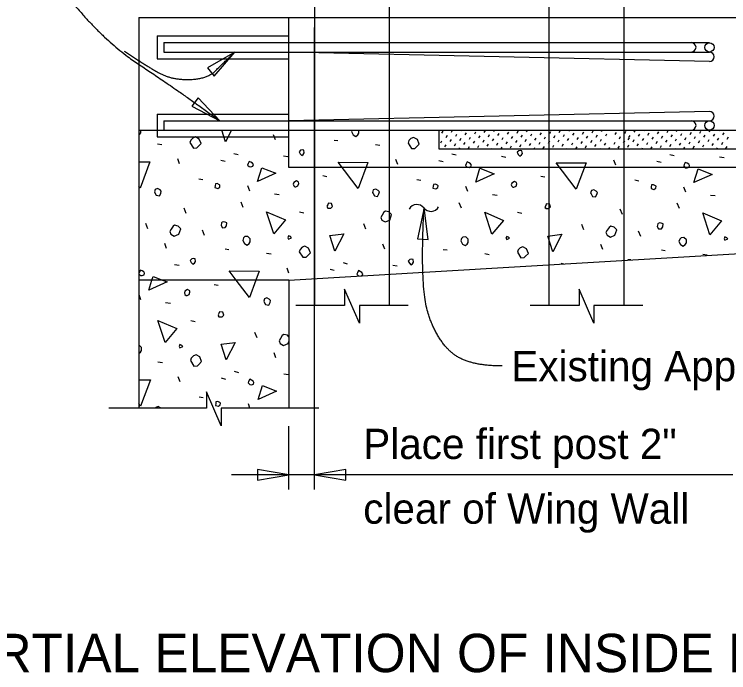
# Model space of a CAD drawing. Extents: x 1.5 to 68.7, y 0 to 31.
# Drawn here: x 5.708 to 10.468, y 8.928 to 13.319 of the extents above; entities that cross this region are included whole.
import ezdxf

# ---------------------------------------------------------------- set-up
doc = ezdxf.new("R2010")
doc.units = 0
for name, color, linetype in [('AdhocPoint_dp', 7, 'Continuous'), ('Border', 7, 'Continuous'), ('Patterning', 7, 'Continuous'), ('PlotBorder_dp', 7, 'Continuous'), ('TextMisc', 7, 'Continuous')]:
    doc.layers.add(name, color=color, linetype=linetype)

msp = doc.modelspace()

# ---------------------------------------------------------------- linework, layer by layer
at = {"layer": 'AdhocPoint_dp'}
for p, q in [((7.7082, 10.1491), (7.7082, 13.2304)), ((7.5373, 10.1491), (7.5373, 10.5717)), ((10.4962, 10.2486), (7.1558, 10.2486))]:
    msp.add_line(p, q, dxfattribs=at)
for points in [[(7.1773, 13.0672), (6.9947, 12.961), (7.0399, 12.9068)], [(7.0775, 12.6089), (6.9327, 12.7627), (6.8901, 12.7064)], [(8.438, 12.0275), (8.3942, 11.8209), (8.4647, 11.818)], [(7.5373, 10.2486), (7.3291, 10.2839), (7.3291, 10.2133)], [(7.7083, 10.2486), (7.9165, 10.2133), (7.9165, 10.2839)]]:
    msp.add_lwpolyline(points, close=True, dxfattribs=at)
for points in [[(8.3333, 11.3762), (8.008, 11.3762), (8.008, 11.2599), (7.9086, 11.4849), (7.9086, 11.3762), (7.5833, 11.3762)], [(9.8958, 11.3762), (9.5705, 11.3762), (9.5705, 11.2599), (9.4711, 11.4849), (9.4711, 11.3762), (9.1458, 11.3762)], [(7.7373, 10.6916), (7.087, 10.6916), (7.087, 10.5754), (6.9877, 10.8004), (6.9877, 10.6916), (6.3373, 10.6916)]]:
    msp.add_lwpolyline(points, dxfattribs=at)
for centre, start, end in [((8.3903, 11.9906), 38.2108, 149.938), ((8.484, 12.0643), 218.2108, 329.938)]:
    msp.add_arc(centre, 0.0596, start, end, dxfattribs=at)
for points in [[(6.8093, 15.9088), (6.0612, 15.8929), (5.9024, 15.7817), (5.8017, 15.236), (5.8706, 13.668), (6.3154, 13.1303), (6.7761, 12.8283), (7.0775, 12.6089)], [(6.4408, 13.0737), (6.5854, 12.9767), (6.7549, 12.8813), (6.9932, 12.8866), (7.1044, 12.9978), (7.1773, 13.0672)], [(8.9586, 10.9737), (8.7125, 10.9737), (8.5074, 11.1744), (8.4117, 11.5165), (8.4379, 12.0275)]]:
    msp.add_open_spline(points, degree=2, dxfattribs=at)
at = {"layer": 'Border'}
for p, q in [((6.704, 13.1297), (10.3395, 13.1297)), ((6.704, 13.1297), (6.704, 13.0672)), ((6.704, 13.0672), (10.3395, 13.0672)), ((10.3395, 13.0048), (7.5373, 13.0672)), ((10.3395, 12.6713), (7.5373, 12.6089)), ((6.704, 12.6089), (10.3395, 12.6089)), ((6.704, 12.6089), (6.704, 12.5464)), ((6.704, 12.5464), (10.3395, 12.5464))]:
    msp.add_line(p, q, dxfattribs=at)
for centre in [(10.3395, 13.0984), (10.3395, 12.5776)]:
    msp.add_circle(centre, 0.0312, dxfattribs=at)
for centre in [(10.2192, 13.0985), (10.3395, 13.036), (10.3395, 13.036), (10.3395, 12.6401), (10.2192, 12.5777)]:
    msp.add_arc(centre, 0.0312, 270, 90, dxfattribs=at)
at = {"layer": 'Patterning'}
for p, q in [((8.5578, 12.5255), (8.5659, 12.5395)), ((8.6213, 12.5336), (8.6287, 12.5464)), ((8.6848, 12.5417), (8.6875, 12.5464)), ((8.7125, 12.514), (8.7206, 12.528)), ((8.776, 12.5221), (8.7841, 12.5361)), ((8.8395, 12.5302), (8.8476, 12.5442)), ((8.903, 12.5383), (8.9076, 12.5464)), ((8.9307, 12.5106), (8.9388, 12.5246)), ((8.9942, 12.5187), (9.0023, 12.5327)), ((9.0577, 12.5268), (9.0658, 12.5408)), ((9.1211, 12.5349), (9.1278, 12.5464)), ((9.1488, 12.5073), (9.1569, 12.5212)), ((9.1846, 12.543), (9.1866, 12.5464)), ((9.2123, 12.5154), (9.2204, 12.5293)), ((9.2758, 12.5235), (9.2839, 12.5374)), ((9.3393, 12.5316), (9.3474, 12.5456)), ((9.4028, 12.5397), (9.4067, 12.5464)), ((9.4305, 12.512), (9.4386, 12.526)), ((9.494, 12.5201), (9.5021, 12.5341)), ((9.5575, 12.5282), (9.5656, 12.5422)), ((9.621, 12.5363), (9.6268, 12.5464)), ((9.6487, 12.5086), (9.6568, 12.5226)), ((9.6845, 12.5444), (9.6856, 12.5464)), ((9.7122, 12.5167), (9.7203, 12.5307)), ((9.7757, 12.5248), (9.7838, 12.5388)), ((9.8392, 12.5329), (9.847, 12.5464)), ((9.9026, 12.541), (9.9058, 12.5464)), ((9.9303, 12.5133), (9.9384, 12.5273)), ((9.9938, 12.5214), (10.0019, 12.5354)), ((10.0573, 12.5295), (10.0654, 12.5435)), ((10.1208, 12.5376), (10.1259, 12.5464)), ((10.1485, 12.5099), (10.1566, 12.5239)), ((10.1843, 12.5457), (10.1847, 12.5464)), ((10.212, 12.518), (10.2201, 12.532)), ((10.2755, 12.5261), (10.2836, 12.5401)), ((10.339, 12.5342), (10.346, 12.5464)), ((10.3667, 12.5065), (10.3748, 12.5205)), ((10.4025, 12.5423), (10.4048, 12.5464)), ((10.4302, 12.5146), (10.4383, 12.5286)), ((7.4477, 12.4815), (7.4354, 12.515)), ((7.8384, 12.4797), (7.8632, 12.4762)), ((8.5497, 12.462), (8.5578, 12.476)), ((8.5855, 12.4978), (8.5936, 12.5118)), ((8.6132, 12.4701), (8.6213, 12.4841)), ((8.649, 12.5059), (8.6571, 12.5199)), ((8.6767, 12.4782), (8.6848, 12.4922)), ((8.7402, 12.4863), (8.7483, 12.5003)), ((8.7679, 12.4586), (8.776, 12.4726)), ((8.8037, 12.4944), (8.8118, 12.5084)), ((8.8314, 12.4667), (8.8395, 12.4807)), ((8.8672, 12.5025), (8.8753, 12.5165)), ((8.8949, 12.4748), (8.903, 12.4888)), ((8.9584, 12.4829), (8.9665, 12.4969)), ((9.0219, 12.491), (9.03, 12.505)), ((9.0496, 12.4634), (9.0577, 12.4773)), ((9.0854, 12.4991), (9.0935, 12.5131)), ((9.113, 12.4715), (9.1211, 12.4854)), ((9.1765, 12.4796), (9.1846, 12.4936)), ((9.24, 12.4877), (9.2481, 12.5017)), ((9.2677, 12.46), (9.2758, 12.474)), ((9.3035, 12.4958), (9.3116, 12.5098)), ((9.3312, 12.4681), (9.3393, 12.4821)), ((9.367, 12.5039), (9.3751, 12.5179)), ((9.3947, 12.4762), (9.4028, 12.4902)), ((9.4582, 12.4843), (9.4663, 12.4983)), ((9.5217, 12.4924), (9.5298, 12.5064)), ((9.5494, 12.4647), (9.5575, 12.4787)), ((9.5852, 12.5005), (9.5933, 12.5145)), ((9.6129, 12.4728), (9.621, 12.4868)), ((9.7399, 12.489), (9.748, 12.503)), ((9.7676, 12.4613), (9.7757, 12.4753)), ((9.7989, 12.4809), (9.807, 12.4949)), ((9.8034, 12.4971), (9.8115, 12.5111)), ((9.8311, 12.4694), (9.8392, 12.4834)), ((9.8669, 12.5052), (9.875, 12.5192)), ((9.8945, 12.4775), (9.9026, 12.4915)), ((9.958, 12.4856), (9.9661, 12.4996)), ((10.0215, 12.4937), (10.0296, 12.5077)), ((10.0492, 12.466), (10.0573, 12.48)), ((10.085, 12.5018), (10.0931, 12.5158)), ((10.1127, 12.4741), (10.1208, 12.4881)), ((10.1762, 12.4822), (10.1843, 12.4962)), ((10.2397, 12.4903), (10.2478, 12.5043)), ((10.2674, 12.4626), (10.2755, 12.4766)), ((10.3032, 12.4984), (10.3113, 12.5124)), ((10.3309, 12.4707), (10.339, 12.4847)), ((10.3944, 12.4788), (10.4025, 12.4928)), ((10.4579, 12.4869), (10.466, 12.5009)), ((6.6611, 12.4549), (6.6911, 12.4496)), ((8.1142, 12.4514), (8.1442, 12.4461)), ((8.5774, 12.4343), (8.5855, 12.4483)), ((8.6409, 12.4424), (8.649, 12.4564)), ((8.6725, 12.4214), (8.6767, 12.4287)), ((8.7044, 12.4505), (8.7125, 12.4645)), ((8.7321, 12.4228), (8.7402, 12.4368)), ((8.7956, 12.4309), (8.8037, 12.4449)), ((8.8591, 12.439), (8.8672, 12.453)), ((8.8926, 12.4214), (8.8949, 12.4253)), ((8.9226, 12.4471), (8.9307, 12.4611)), ((8.9514, 12.4214), (8.9584, 12.4334)), ((8.9861, 12.4552), (8.9942, 12.4692)), ((9.0138, 12.4276), (9.0219, 12.4415)), ((9.0772, 12.4357), (9.0854, 12.4497)), ((9.1407, 12.4438), (9.1488, 12.4578)), ((9.1715, 12.4214), (9.1765, 12.4301)), ((9.2042, 12.4519), (9.2123, 12.4659)), ((9.2319, 12.4242), (9.24, 12.4382)), ((9.2954, 12.4323), (9.3035, 12.4463)), ((9.3589, 12.4404), (9.367, 12.4544)), ((9.3917, 12.4214), (9.3947, 12.4267)), ((9.4224, 12.4485), (9.4305, 12.4625)), ((9.4505, 12.4214), (9.4582, 12.4348)), ((9.4859, 12.4566), (9.494, 12.4706)), ((9.5136, 12.4289), (9.5217, 12.4429)), ((9.5771, 12.437), (9.5852, 12.451)), ((9.6406, 12.4451), (9.6487, 12.4591)), ((9.6706, 12.4214), (9.6764, 12.4314)), ((9.7041, 12.4532), (9.7122, 12.4672)), ((9.7318, 12.4255), (9.7399, 12.4395)), ((9.7953, 12.4336), (9.8034, 12.4476)), ((9.8587, 12.4417), (9.8669, 12.4557)), ((9.8907, 12.4214), (9.8945, 12.428)), ((9.9222, 12.4498), (9.9303, 12.4638)), ((9.9499, 12.4221), (9.958, 12.4361)), ((9.9857, 12.4579), (9.9938, 12.4719)), ((10.0134, 12.4302), (10.0215, 12.4442)), ((10.0769, 12.4383), (10.085, 12.4523)), ((10.1404, 12.4464), (10.1485, 12.4604)), ((10.1697, 12.4214), (10.1762, 12.4327)), ((10.2039, 12.4545), (10.212, 12.4685)), ((10.2316, 12.4268), (10.2397, 12.4408)), ((10.2951, 12.4349), (10.3032, 12.4489)), ((10.3586, 12.443), (10.3667, 12.457)), ((10.3898, 12.4214), (10.3944, 12.4293)), ((10.4221, 12.4511), (10.4302, 12.4651)), ((10.4498, 12.4234), (10.4579, 12.4374)), ((7.1702, 12.3913), (7.1985, 12.3842)), ((8.6233, 12.3878), (8.6516, 12.3807)), ((9.1127, 12.4214), (9.113, 12.422)), ((9.6118, 12.4214), (9.6129, 12.4233)), ((10.0764, 12.3842), (10.1047, 12.3772)), ((10.1109, 12.4214), (10.1127, 12.4246)), ((6.8096, 12.3206), (6.7972, 12.3542)), ((7.0836, 12.3471), (7.1119, 12.34)), ((7.5008, 12.3754), (7.5308, 12.3701)), ((8.2627, 12.3171), (8.2503, 12.3506)), ((8.5367, 12.3436), (8.565, 12.3365)), ((8.9539, 12.3719), (8.9839, 12.3665)), ((9.7158, 12.3135), (9.7034, 12.3471)), ((9.9898, 12.34), (10.0181, 12.333)), ((10.407, 12.3683), (10.437, 12.363)), ((7.7642, 12.2428), (7.7907, 12.2375)), ((9.2173, 12.2393), (9.2438, 12.234)), ((6.9369, 12.2216), (6.9634, 12.2163)), ((8.39, 12.2181), (8.4165, 12.2128)), ((9.8431, 12.2145), (9.8696, 12.2092)), ((7.2763, 12.1403), (7.2639, 12.1739)), ((8.7294, 12.1367), (8.717, 12.1703)), ((10.1825, 12.1332), (10.1701, 12.1668)), ((7.4407, 12.1208), (7.4725, 12.1173)), ((8.8938, 12.1173), (8.9256, 12.1138)), ((10.3469, 12.1138), (10.3787, 12.1102)), ((7.2338, 12.0307), (7.2197, 12.066)), ((8.6869, 12.0271), (8.6728, 12.0625)), ((10.1401, 12.0236), (10.1259, 12.059)), ((6.8538, 11.99), (6.8396, 12.0254)), ((7.6086, 12.0024), (7.6369, 11.9953)), ((9.0617, 11.9989), (9.09, 11.9918)), ((9.76, 11.9829), (9.7458, 12.0183)), ((6.5974, 11.8893), (6.5833, 11.9246)), ((8.0506, 11.8857), (8.0364, 11.9211)), ((9.5037, 11.8822), (9.4895, 11.9175)), ((6.9758, 11.8433), (6.9616, 11.8786)), ((9.882, 11.8362), (9.8678, 11.8716)), ((6.723, 11.7567), (6.7106, 11.7903)), ((8.1761, 11.7531), (8.1637, 11.7867)), ((9.6292, 11.7496), (9.6168, 11.7832)), ((7.1136, 11.7549), (7.1384, 11.7514)), ((7.3894, 11.7266), (7.4195, 11.7213)), ((8.5667, 11.7514), (8.5915, 11.7478)), ((8.8425, 11.7231), (8.8726, 11.7178)), ((10.0198, 11.7478), (10.0446, 11.7443)), ((10.2956, 11.7195), (10.3257, 11.7142)), ((6.776, 11.6506), (6.806, 11.6453)), ((7.5379, 11.5923), (7.5255, 11.6259)), ((7.8119, 11.6188), (7.8402, 11.6117)), ((7.8985, 11.663), (7.9268, 11.6559)), ((8.2291, 11.6471), (8.2591, 11.6418)), ((9.3516, 11.6594), (9.3698, 11.6549)), ((7.0394, 11.518), (7.0659, 11.5127)), ((6.5515, 11.4155), (6.5391, 11.4491)), ((6.7159, 11.396), (6.7477, 11.3925)), ((6.8838, 11.2776), (6.9121, 11.2705)), ((7.3258, 11.1609), (7.3116, 11.1963)), ((7.4513, 11.0283), (7.4389, 11.0619)), ((6.6646, 11.0018), (6.6947, 10.9965)), ((7.1737, 10.9382), (7.202, 10.9311)), ((7.5043, 10.9223), (7.5344, 10.917)), ((6.8131, 10.8675), (6.8007, 10.9011)), ((7.0871, 10.894), (7.1154, 10.8869)), ((6.9404, 10.7685), (6.9669, 10.7632)), ((7.2782, 10.6916), (7.2674, 10.7208))]:
    msp.add_line(p, q, dxfattribs=at)
for points in [[(8.2082, 11.3761), (8.2082, 15.1963), (7.7082, 15.1963), (7.7082, 11.3761)], [(9.7707, 11.3761), (9.7707, 15.1963), (9.2707, 15.1963), (9.2707, 11.3761)], [(6.5373, 12.5133), (6.5444, 12.5186), (6.5515, 12.5292), (6.5515, 12.5464)], [(7.1154, 12.4673), (7.0899, 12.5464)], [(7.1561, 12.5464), (7.1154, 12.4673)], [(7.9551, 12.5363), (7.9657, 12.515), (7.9834, 12.5044), (7.9975, 12.515), (8.0046, 12.5256), (8.0046, 12.5464)], [(7.9585, 12.5464), (7.9551, 12.5363)], [(8.2601, 12.5464), (8.2609, 12.5451)], [(8.2609, 12.5451), (8.2638, 12.5464)], [(6.8785, 12.4638), (6.9015, 12.4267), (6.9245, 12.4284), (6.9333, 12.4373), (6.9528, 12.4567), (6.9404, 12.4868), (6.9156, 12.5009), (6.898, 12.4938), (6.8838, 12.4797), (6.8785, 12.4638)], [(8.3316, 12.4602), (8.3546, 12.4231), (8.3776, 12.4249), (8.3864, 12.4337), (8.4059, 12.4532), (8.3935, 12.4832), (8.3688, 12.4974), (8.3511, 12.4903), (8.3369, 12.4762), (8.3316, 12.4602)], [(7.6121, 12.3878), (7.6228, 12.3772), (7.6334, 12.3842), (7.6404, 12.3948), (7.6369, 12.4125), (7.6281, 12.4143), (7.6157, 12.4125), (7.6051, 12.4019), (7.6121, 12.3878)], [(9.0653, 12.3842), (9.0759, 12.3736), (9.0865, 12.3807), (9.0935, 12.3913), (9.09, 12.409), (9.0812, 12.4107), (9.0688, 12.409), (9.0582, 12.3984), (9.0653, 12.3842)], [(9.8066, 12.4214), (9.8077, 12.4196), (9.8307, 12.4213), (9.8307, 12.4214)], [(6.5373, 12.3354), (6.6116, 12.3347), (6.5462, 12.1597)], [(7.2727, 12.3029), (7.2851, 12.3011), (7.2975, 12.3064), (7.301, 12.3171), (7.2957, 12.3259), (7.2851, 12.333), (7.2727, 12.3383), (7.2657, 12.3241), (7.2621, 12.3135), (7.2727, 12.3029)], [(7.9993, 12.1562), (7.8649, 12.333), (8.0647, 12.3312), (7.9993, 12.1562)], [(8.7258, 12.2994), (8.7382, 12.2976), (8.7506, 12.3029), (8.7541, 12.3135), (8.7488, 12.3224), (8.7382, 12.3294), (8.7258, 12.3347), (8.7188, 12.3206), (8.7152, 12.31), (8.7258, 12.2994)], [(10.1789, 12.2958), (10.1913, 12.2941), (10.2037, 12.2994), (10.2072, 12.31), (10.2019, 12.3188), (10.1913, 12.3259), (10.1789, 12.3312), (10.1719, 12.3171), (10.1683, 12.3064), (10.1789, 12.2958)], [(7.3293, 12.2039), (7.3576, 12.2958), (7.4513, 12.2587), (7.3293, 12.2039)], [(8.7824, 12.2004), (8.8107, 12.2923), (8.9044, 12.2552), (8.7824, 12.2004)], [(9.4524, 12.1526), (9.318, 12.3294), (9.5178, 12.3277), (9.4524, 12.1526)], [(10.2355, 12.1968), (10.2638, 12.2888), (10.3575, 12.2516), (10.2355, 12.1968)], [(7.0447, 12.1633), (7.0641, 12.158), (7.0765, 12.1668), (7.0783, 12.1792), (7.0747, 12.1827), (7.0606, 12.1898), (7.0482, 12.188), (7.0465, 12.1756), (7.0447, 12.1633)], [(7.5768, 12.1686), (7.5839, 12.1686), (7.598, 12.1756), (7.6033, 12.1915), (7.6015, 12.2004), (7.5874, 12.2074), (7.5697, 12.1968), (7.5662, 12.1862), (7.5697, 12.1756), (7.5768, 12.1686)], [(9.0299, 12.165), (9.037, 12.165), (9.0511, 12.1721), (9.0564, 12.188), (9.0546, 12.1968), (9.0405, 12.2039), (9.0228, 12.1933), (9.0193, 12.1827), (9.0228, 12.1721), (9.0299, 12.165)], [(6.5462, 12.1597), (6.5373, 12.1713)], [(6.6452, 12.1279), (6.654, 12.112), (6.6752, 12.1085), (6.6841, 12.1244), (6.6876, 12.1385), (6.6788, 12.1473), (6.6629, 12.1562), (6.6469, 12.1509), (6.6416, 12.135), (6.6452, 12.1279)], [(8.0983, 12.1244), (8.1071, 12.1085), (8.1283, 12.1049), (8.1372, 12.1208), (8.1407, 12.135), (8.1319, 12.1438), (8.116, 12.1526), (8.1001, 12.1473), (8.0947, 12.1314), (8.0983, 12.1244)], [(8.4978, 12.1597), (8.5172, 12.1544), (8.5296, 12.1633), (8.5314, 12.1756), (8.5279, 12.1792), (8.5137, 12.1862), (8.5013, 12.1845), (8.4996, 12.1721), (8.4978, 12.1597)], [(9.5514, 12.1208), (9.5602, 12.1049), (9.5814, 12.1014), (9.5903, 12.1173), (9.5938, 12.1314), (9.585, 12.1403), (9.5691, 12.1491), (9.5532, 12.1438), (9.5479, 12.1279), (9.5514, 12.1208)], [(9.9509, 12.1562), (9.9703, 12.1509), (9.9827, 12.1597), (9.9845, 12.1721), (9.981, 12.1756), (9.9668, 12.1827), (9.9544, 12.1809), (9.9527, 12.1686), (9.9509, 12.1562)], [(7.796, 12.0271), (7.8172, 12.0271), (7.8278, 12.0377), (7.8225, 12.0572), (7.7995, 12.059), (7.796, 12.0484), (7.7907, 12.0395), (7.796, 12.0271), (7.7925, 12.0307)], [(9.2491, 12.0236), (9.2703, 12.0236), (9.2809, 12.0342), (9.2756, 12.0537), (9.2526, 12.0554), (9.2491, 12.0448), (9.2438, 12.036), (9.2491, 12.0236), (9.2456, 12.0271)], [(7.4371, 11.8557), (7.3894, 12.0024), (7.5149, 11.9476), (7.4371, 11.8557)], [(8.1563, 11.9467), (8.1793, 11.9344), (8.2094, 11.9467), (8.2217, 11.9839), (8.2041, 12.0015), (8.1811, 12.0069), (8.1705, 11.9998), (8.1581, 11.9803), (8.1493, 11.9644), (8.1563, 11.9467)], [(8.8902, 11.8521), (8.8425, 11.9989), (8.968, 11.9441), (8.8902, 11.8521)], [(10.3433, 11.8486), (10.2956, 11.9953), (10.4211, 11.9405), (10.3433, 11.8486)], [(6.7512, 11.8521), (6.7742, 11.8398), (6.8043, 11.8521), (6.8167, 11.8893), (6.799, 11.9069), (6.776, 11.9122), (6.7654, 11.9052), (6.753, 11.8857), (6.7442, 11.8698), (6.7512, 11.8521)], [(7.0854, 11.9105), (7.0942, 11.8946), (7.1136, 11.8963), (7.1225, 11.9087), (7.1242, 11.9281), (7.1119, 11.9334), (7.103, 11.9352), (7.0924, 11.9317), (7.0889, 11.9281), (7.0854, 11.9105)], [(9.6575, 11.8451), (9.6804, 11.8327), (9.7105, 11.8451), (9.7229, 11.8822), (9.7052, 11.8999), (9.6822, 11.9052), (9.6716, 11.8981), (9.6592, 11.8786), (9.6504, 11.8627), (9.6575, 11.8451)], [(9.9916, 11.9034), (10.0004, 11.8875), (10.0198, 11.8893), (10.0287, 11.9016), (10.0305, 11.9211), (10.0181, 11.9264), (10.0092, 11.9281), (9.9986, 11.9246), (9.9951, 11.9211), (9.9916, 11.9034)], [(7.8437, 11.739), (7.8101, 11.8433), (7.9038, 11.8557), (7.8437, 11.739)], [(7.2303, 11.8115), (7.2409, 11.7903), (7.2586, 11.7797), (7.2727, 11.7903), (7.2798, 11.8009), (7.2798, 11.8221), (7.2639, 11.838), (7.2445, 11.8362), (7.2356, 11.8274), (7.2303, 11.8115)], [(7.5361, 11.8203), (7.5556, 11.8291), (7.5485, 11.8362), (7.5361, 11.8415), (7.5308, 11.8291), (7.5361, 11.8203)], [(8.6834, 11.8079), (8.694, 11.7867), (8.7117, 11.7761), (8.7258, 11.7867), (8.7329, 11.7973), (8.7329, 11.8185), (8.717, 11.8345), (8.6976, 11.8327), (8.6887, 11.8238), (8.6834, 11.8079)], [(8.9892, 11.8168), (9.0087, 11.8256), (9.0016, 11.8327), (8.9892, 11.838), (8.9839, 11.8256), (8.9892, 11.8168)], [(9.2968, 11.7355), (9.2632, 11.8398), (9.3569, 11.8521), (9.2968, 11.7355)], [(10.1365, 11.8044), (10.1471, 11.7832), (10.1648, 11.7726), (10.1789, 11.7832), (10.186, 11.7938), (10.186, 11.815), (10.1701, 11.8309), (10.1507, 11.8291), (10.1418, 11.8203), (10.1365, 11.8044)], [(10.4423, 11.8132), (10.4618, 11.8221), (10.4547, 11.8291), (10.4423, 11.8345), (10.437, 11.8221), (10.4423, 11.8132)], [(7.6068, 11.7355), (7.6298, 11.6983), (7.6528, 11.7001), (7.6616, 11.7089), (7.6811, 11.7284), (7.6687, 11.7584), (7.644, 11.7726), (7.6263, 11.7655), (7.6121, 11.7514), (7.6068, 11.7355)], [(9.0599, 11.7319), (9.0829, 11.6948), (9.1059, 11.6966), (9.1147, 11.7054), (9.1342, 11.7248), (9.1218, 11.7549), (9.0971, 11.769), (9.0794, 11.762), (9.0653, 11.7478), (9.0599, 11.7319)], [(6.8874, 11.663), (6.898, 11.6524), (6.9086, 11.6594), (6.9156, 11.67), (6.9121, 11.6877), (6.9033, 11.6895), (6.8909, 11.6877), (6.8803, 11.6771), (6.8874, 11.663)], [(8.3405, 11.6594), (8.3511, 11.6488), (8.3617, 11.6559), (8.3688, 11.6665), (8.3652, 11.6842), (8.3564, 11.686), (8.344, 11.6842), (8.3334, 11.6736), (8.3405, 11.6594)], [(9.8152, 11.6813), (9.8095, 11.6824), (9.7971, 11.6807), (9.7966, 11.6802)], [(6.548, 11.5781), (6.5603, 11.5764), (6.5727, 11.5817), (6.5762, 11.5923), (6.5709, 11.6011), (6.5603, 11.6082), (6.548, 11.6135), (6.5409, 11.5993), (6.5373, 11.5887)], [(6.5373, 11.5887), (6.548, 11.5781)], [(6.6252, 11.5463), (6.6328, 11.5711), (6.6953, 11.5463)], [(7.1872, 11.5463), (7.1402, 11.6082), (7.3399, 11.6064), (7.3175, 11.5463)], [(8.0181, 11.5748), (8.0258, 11.5781), (8.0293, 11.5887), (8.024, 11.5976), (8.0134, 11.6046), (8.0011, 11.6099), (7.994, 11.5958), (7.9904, 11.5852), (8.0011, 11.5746)], [(8.0011, 11.5746), (8.0049, 11.574)], [(6.6045, 11.4791), (6.6252, 11.5463)], [(6.6953, 11.5463), (6.7265, 11.5339), (6.6045, 11.4791)], [(7.2745, 11.4314), (7.1872, 11.5463)], [(7.3174, 11.5463), (7.2745, 11.4314)], [(6.852, 11.4438), (6.8591, 11.4438), (6.8732, 11.4508), (6.8785, 11.4668), (6.8768, 11.4756), (6.8626, 11.4827), (6.8449, 11.4721), (6.8414, 11.4615), (6.8449, 11.4508), (6.852, 11.4438)], [(7.3735, 11.3996), (7.3823, 11.3837), (7.4036, 11.3801), (7.4124, 11.396), (7.4159, 11.4102), (7.4071, 11.419), (7.3912, 11.4279), (7.3753, 11.4226), (7.37, 11.4067), (7.3735, 11.3996)], [(7.0712, 11.3024), (7.0924, 11.3024), (7.103, 11.313), (7.0977, 11.3324), (7.0747, 11.3342), (7.0712, 11.3236), (7.0659, 11.3147), (7.0712, 11.3024), (7.0677, 11.3059)], [(6.7124, 11.1309), (6.6646, 11.2776), (6.7901, 11.2228), (6.7124, 11.1309)], [(7.5373, 11.1686), (7.5273, 11.1786), (7.5043, 11.1839), (7.4937, 11.1768), (7.4813, 11.1574), (7.4725, 11.1415), (7.4796, 11.1238)], [(6.5373, 11.0575), (6.548, 11.0655), (6.555, 11.0761), (6.555, 11.0973), (6.5391, 11.1132), (6.5373, 11.113)], [(6.8113, 11.0955), (6.8308, 11.1044), (6.8237, 11.1114), (6.8113, 11.1167), (6.806, 11.1044), (6.8113, 11.0955)], [(7.1189, 11.0142), (7.0854, 11.1185), (7.179, 11.1309), (7.1189, 11.0142)], [(7.4796, 11.1238), (7.5025, 11.1114), (7.5326, 11.1238), (7.5373, 11.1381)], [(6.8821, 11.0107), (6.905, 10.9735), (6.928, 10.9753), (6.9369, 10.9842), (6.9563, 11.0036), (6.9439, 11.0337), (6.9192, 11.0478), (6.9015, 11.0407), (6.8874, 11.0266), (6.8821, 11.0107)], [(6.5373, 10.8823), (6.6151, 10.8816), (6.5497, 10.7066)], [(7.2763, 10.8498), (7.2886, 10.848), (7.301, 10.8533), (7.3046, 10.8639), (7.2993, 10.8728), (7.2886, 10.8799), (7.2763, 10.8852), (7.2692, 10.871), (7.2657, 10.8604), (7.2763, 10.8498)], [(7.3328, 10.7508), (7.3611, 10.8427), (7.4548, 10.8056), (7.3328, 10.7508)], [(6.5497, 10.7066), (6.5373, 10.7229)], [(7.0482, 10.7102), (7.0677, 10.7048), (7.08, 10.7137), (7.0818, 10.7261), (7.0783, 10.7296), (7.0641, 10.7367), (7.0518, 10.7349), (7.05, 10.7225), (7.0482, 10.7102)], [(6.6849, 10.6916), (6.6823, 10.6942), (6.6664, 10.7031), (6.6505, 10.6978), (6.6484, 10.6916)]]:
    msp.add_lwpolyline(points, dxfattribs=at)
at = {"layer": 'PlotBorder_dp'}
for p, q in [((6.5373, 13.2964), (6.5373, 10.6916)), ((6.5373, 13.2964), (7.5373, 13.2964)), ((7.5373, 13.2964), (10.5373, 13.2964)), ((7.5373, 12.5464), (7.5373, 13.2964)), ((6.6595, 13.1742), (6.6595, 13.0228)), ((6.6595, 13.1742), (7.5373, 13.1742)), ((6.6595, 13.0228), (7.5373, 13.0228)), ((6.6595, 12.6533), (6.6595, 12.5019)), ((6.6595, 12.6533), (7.5373, 12.6533)), ((6.5373, 12.5464), (12.2608, 12.5464)), ((8.5374, 12.5464), (8.5374, 12.4214)), ((6.6595, 12.5019), (7.5373, 12.5019)), ((8.5374, 12.4214), (12.2608, 12.4214)), ((7.5373, 11.5463), (11.7573, 11.7963)), ((7.5373, 11.5463), (6.5373, 11.5463)), ((7.5373, 11.5463), (7.5373, 10.6916))]:
    msp.add_line(p, q, dxfattribs=at)
msp.add_lwpolyline([(10.5373, 12.5464), (10.5373, 12.2964), (7.5373, 12.2964), (7.5373, 12.5464)], dxfattribs=at)

# ---------------------------------------------------------------- texts
at = {"layer": 'AdhocPoint_dp'}
msp.add_text('PARTIAL ELEVATION OF INSIDE FACE OF GUARDRAIL', height=0.256001, dxfattribs=at).set_placement((5.1193, 8.9321))
at = {"layer": 'TextMisc'}
for s, p in [('Existing Approach Slab', (9.0197, 10.8719)), ('Place first post 2"', (8.033, 10.3536)), ('clear of Wing Wall', (8.033, 9.922))]:
    msp.add_text(s, height=0.2016, dxfattribs=at).set_placement(p)

doc.saveas('drawing.dxf')
